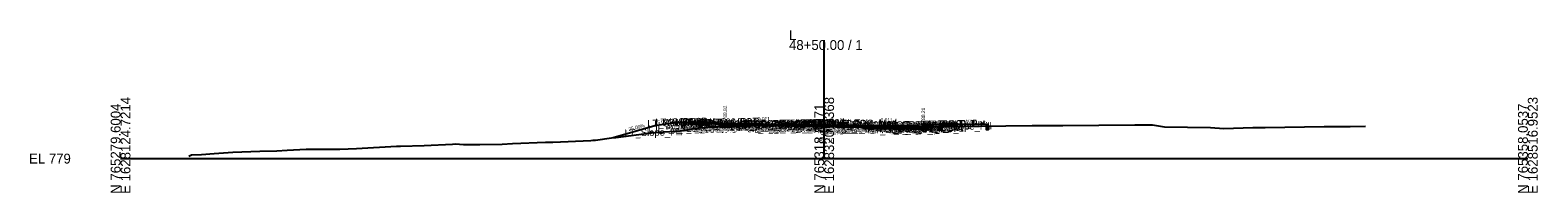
# Model space of a CAD drawing. Extents: x -26 to 4403, y -510 to 9556.
# Drawn here: x 2974.3 to 3402.8, y 8490.3 to 8536.4 of the extents above; entities that cross this region are included whole.
import ezdxf

# ---------------------------------------------------------------- set-up
doc = ezdxf.new("R2010")
doc.units = 0
for name, color, linetype in [('Default', 7, 'Continuous'), ('Exist CMT Pavement', 7, 'Continuous'), ('Exist Cross Section Cell', 7, 'Continuous'), ('Exist XS Center Line Elevation Label', 7, 'Continuous'), ('Exist XS Ground Line', 7, 'Continuous'), ('Prop CMT Conc Surface', 7, 'Continuous'), ('Prop CMT Concrete Structures', 7, 'Continuous'), ('Prop CMT Pvmt Course 1', 7, 'Continuous'), ('Prop CMT Pvmt Course 1 CG', 7, 'Continuous'), ('Prop CMT Pvmt Course 2', 7, 'Continuous'), ('Prop CMT Pvmt Course 2 Wedge', 7, 'Continuous'), ('Prop CMT Pvmt Course 3', 7, 'Continuous'), ('Prop CMT Pvmt Course 3 Wedge', 7, 'Continuous'), ('Prop CMT Pvmt Surface', 7, 'Continuous'), ('Prop CMT Slope Grass', 7, 'Continuous'), ('Prop CMT Subgrade Earthwork', 7, 'Continuous'), ('Prop XS Finish Grade CurbGutter', 7, 'Continuous'), ('Prop XS Hydro Elevations', 7, 'Continuous'), ('Prop XS SE Text', 7, 'Continuous'), ('Prop XS Side Slope Text', 7, 'Continuous'), ('Scratch_Level_0', 7, 'Continuous')]:
    doc.layers.add(name, color=color, linetype=linetype)

msp = doc.modelspace()

# ---------------------------------------------------------------- linework, layer by layer
at = {"layer": 'Exist CMT Pavement'}
for points in [[(3173.85, 8509.18), (3174.11, 8509.18), (3182.2, 8509.38), (3190.56, 8509.3), (3191.23, 8509.29)], [(3208.77, 8508.96), (3209.39, 8508.97), (3211.08, 8508.98)]]:
    msp.add_lwpolyline(points, dxfattribs=at)
at = {"layer": 'Exist Cross Section Cell'}
for p, q in [((3200, 8500), (3200, 8533.6)), ((3000, 8500), (3200, 8500)), ((3200, 8500), (3400, 8500))]:
    msp.add_line(p, q, dxfattribs=at)
at = {"layer": 'Exist XS Ground Line'}
msp.add_lwpolyline([(3019.39, 8500.67), (3020.16, 8501.04), (3022.97, 8501.2), (3026.61, 8501.44), (3031.94, 8501.81), (3034.49, 8501.96), (3039.59, 8502.09), (3044.44, 8502.17), (3047.32, 8502.39), (3052.78, 8502.71), (3062.34, 8502.68), (3067.05, 8502.9), (3078.43, 8503.49), (3079.57, 8503.52), (3086.29, 8503.75), (3094.36, 8504.13), (3095.16, 8504.14), (3097.51, 8504.01), (3101.17, 8504.01), (3102.14, 8503.99), (3108.47, 8504.07), (3111.41, 8504.32), (3120.76, 8504.62), (3122.88, 8504.69), (3133.66, 8505.11), (3134.31, 8505.21), (3134.97, 8505.27), (3139.58, 8505.85), (3140.77, 8506.02), (3150.92, 8507.33), (3152.79, 8507.48), (3157.72, 8507.73), (3159.04, 8507.89), (3164.97, 8508.77), (3165.57, 8508.68), (3167.07, 8509), (3167.64, 8509.02), (3174.11, 8509.18), (3182.2, 8509.38), (3190.56, 8509.3), (3194.45, 8509.27), (3198.03, 8509.16), (3200, 8509.1), (3206.63, 8508.9), (3209.39, 8508.97), (3237.06, 8509.1), (3241, 8509.17), (3244.18, 8509.2), (3259.12, 8509.37), (3267.85, 8509.39), (3288.26, 8509.53), (3290, 8509.53), (3293.32, 8509.56), (3293.84, 8509.47), (3296.68, 8509), (3309.78, 8508.84), (3313.57, 8508.54), (3321.79, 8508.81), (3325.37, 8508.79), (3342.1, 8509.06), (3348.41, 8509.06), (3349.47, 8509.06), (3353.89, 8509.21)], dxfattribs=at)
at = {"layer": 'Prop CMT Conc Surface'}
for points in [[(3173.85, 8509.88), (3171.85, 8509.82)], [(3226.15, 8509.31), (3228.15, 8509.21)], [(3228.15, 8509.21), (3228.15, 8509.71), (3228.65, 8509.71)], [(3232.66, 8509.8), (3237.66, 8509.9)]]:
    msp.add_lwpolyline(points, dxfattribs=at)
at = {"layer": 'Prop CMT Concrete Structures'}
for p, q in [((3151.85, 8509.25), (3140, 8505.91)), ((3156.85, 8510), (3151.85, 8509.25)), ((3161.85, 8510.2), (3156.85, 8510)), ((3167.35, 8510.09), (3161.85, 8510.2)), ((3171.35, 8509.93), (3167.35, 8510.09)), ((3171.85, 8509.82), (3171.35, 8509.93))]:
    msp.add_line(p, q, dxfattribs=at)
for points in [[(3162.34, 8509.86), (3162.34, 8510.19)], [(3167.34, 8509.76), (3162.34, 8509.86)], [(3167.34, 8510.09), (3167.34, 8509.76)], [(3171.35, 8509.93), (3171.35, 8509.32), (3173.85, 8509.3)], [(3173.85, 8509.3), (3173.85, 8509.88)], [(3226.15, 8509.31), (3228.15, 8509.21), (3228.15, 8509.71), (3228.65, 8509.71)], [(3228.65, 8509.71), (3228.65, 8508.7), (3226.15, 8508.73)], [(3226.15, 8508.73), (3226.15, 8509.31)], [(3237.66, 8509.9), (3232.66, 8509.8)], [(3232.66, 8509.8), (3232.66, 8509.47)], [(3232.66, 8509.47), (3237.66, 8509.57)], [(3237.66, 8509.57), (3237.66, 8509.9)]]:
    msp.add_lwpolyline(points, dxfattribs=at)
at = {"layer": 'Prop CMT Pvmt Course 1'}
for points in [[(3200, 8509.6), (3173.85, 8509.88)], [(3173.85, 8509.88), (3173.85, 8509.63), (3173.85, 8509.63)], [(3173.85, 8509.63), (3200, 8509.35)], [(3200, 8509.6), (3226.15, 8509.31)], [(3200, 8509.35), (3200, 8509.6)], [(3226.15, 8509.06), (3211.09, 8509.22), (3200, 8509.35)], [(3200, 8509.35), (3200, 8509.35)], [(3208.75, 8509.25), (3208.75, 8509.25)], [(3226.15, 8509.31), (3226.15, 8509.06)]]:
    msp.add_lwpolyline(points, dxfattribs=at)
at = {"layer": 'Prop CMT Pvmt Course 1 CG'}
for points in [[(3173.85, 8509.3), (3170.85, 8509.33), (3170.52, 8509)], [(3170.52, 8509), (3173.85, 8508.96)], [(3173.85, 8508.96), (3173.85, 8509.3)], [(3226.15, 8508.73), (3229.15, 8508.7), (3229.49, 8508.36)], [(3226.15, 8508.4), (3226.15, 8508.73)], [(3229.49, 8508.36), (3226.15, 8508.4)]]:
    msp.add_lwpolyline(points, dxfattribs=at)
at = {"layer": 'Prop CMT Pvmt Course 2'}
for points in [[(3173.85, 8509.3), (3173.85, 8509.3), (3173.85, 8509.63), (3173.85, 8509.63)], [(3173.85, 8509.63), (3173.85, 8509.3)], [(3200, 8509.35), (3200, 8509.35)], [(3208.75, 8509.25), (3208.75, 8509.25)], [(3211.09, 8508.89), (3211.09, 8509.22)], [(3211.09, 8509.22), (3226.15, 8509.06)], [(3226.15, 8508.73), (3211.09, 8508.89)], [(3226.15, 8509.06), (3226.15, 8508.73)]]:
    msp.add_lwpolyline(points, dxfattribs=at)
at = {"layer": 'Prop CMT Pvmt Course 2 Wedge'}
for points in [[(3173.85, 8509.63), (3174.11, 8509.63), (3182.2, 8509.54), (3190.56, 8509.45), (3200, 8509.35)], [(3173.85, 8509.29), (3173.85, 8509.63)], [(3191.23, 8509.29), (3190.56, 8509.3), (3182.2, 8509.38), (3177.16, 8509.26), (3174.11, 8509.29), (3173.85, 8509.29)], [(3200, 8509.35), (3200, 8509.1)], [(3200, 8509.35), (3209.39, 8509.24), (3211.09, 8509.22)], [(3211.09, 8508.98), (3209.39, 8508.97), (3208.75, 8508.96)], [(3211.09, 8509.22), (3211.09, 8508.98)]]:
    msp.add_lwpolyline(points, dxfattribs=at)
at = {"layer": 'Prop CMT Pvmt Course 3'}
for points in [[(3173.85, 8509.3), (3173.85, 8509.3), (3173.85, 8508.96), (3173.85, 8508.96)], [(3173.85, 8508.96), (3173.85, 8509.3)], [(3211.09, 8508.89), (3226.15, 8508.73)], [(3211.09, 8508.56), (3211.09, 8508.89)], [(3226.15, 8508.4), (3211.09, 8508.56)], [(3226.15, 8508.73), (3226.15, 8508.4)]]:
    msp.add_lwpolyline(points, dxfattribs=at)
at = {"layer": 'Prop CMT Pvmt Course 3 Wedge'}
for points in [[(3173.85, 8509.3), (3174.11, 8509.29), (3177.17, 8509.26)], [(3173.85, 8509.18), (3173.85, 8509.3)], [(3177.17, 8509.26), (3174.11, 8509.18), (3173.85, 8509.18)]]:
    msp.add_lwpolyline(points, dxfattribs=at)
at = {"layer": 'Prop CMT Pvmt Surface'}
for points in [[(3200, 8509.6), (3173.85, 8509.88)], [(3200, 8509.6), (3226.15, 8509.31)]]:
    msp.add_lwpolyline(points, dxfattribs=at)
at = {"layer": 'Prop CMT Slope Grass'}
for p, q in [((3228.65, 8509.71), (3238.15, 8509.9)), ((3238.15, 8509.9), (3245.99, 8509.72))]:
    msp.add_line(p, q, dxfattribs=at)
msp.add_lwpolyline([(3245.99, 8509.72), (3245.99, 8508.23), (3246.66, 8508.23), (3246.66, 8509.22)], dxfattribs=at)
at = {"layer": 'Prop CMT Subgrade Earthwork'}
for points in [[(3173.85, 8508.96), (3170.52, 8509), (3169.51, 8510)], [(3173.85, 8508.96), (3173.85, 8509.18)], [(3173.85, 8508.96), (3173.85, 8508.96)], [(3173.85, 8508.96), (3173.85, 8508.96)], [(3211.09, 8508.56), (3211.08, 8508.98)], [(3211.09, 8508.56), (3226.15, 8508.4)], [(3226.15, 8508.4), (3229.49, 8508.36), (3230.89, 8509.76)], [(3226.15, 8508.4), (3226.15, 8508.4)]]:
    msp.add_lwpolyline(points, dxfattribs=at)
at = {"layer": 'Prop XS Finish Grade CurbGutter'}
for p, q in [((3245.99, 8509.72), (3246.19, 8509.72)), ((3245.99, 8509.72), (3246.66, 8509.72)), ((3245.99, 8509.72), (3245.99, 8508.73)), ((3245.99, 8508.73), (3245.99, 8508.23)), ((3245.99, 8508.73), (3246.66, 8508.73)), ((3245.99, 8508.23), (3246.66, 8508.23)), ((3246.66, 8509.31), (3246.31, 8509.67)), ((3246.66, 8509.31), (3246.66, 8508.73)), ((3246.66, 8509.22), (3246.66, 8509.22)), ((3246.66, 8508.73), (3246.66, 8508.23))]:
    msp.add_line(p, q, dxfattribs=at)
msp.add_arc((3246.19, 8509.56), 0.166, 43.9997, 90, dxfattribs=at)

# ---------------------------------------------------------------- texts
at = {"layer": 'Default'}
msp.add_text('-', height=0.0001, dxfattribs=at).set_placement((3000, 8500))
at = {"layer": 'Exist Cross Section Cell'}
for s, p in [('L', (3190, 8533.6)), ('48+50.00 / 1', (3190, 8530.8)), ('EL 779', (2974, 8498.6))]:
    msp.add_text(s, height=2.8, dxfattribs=at).set_placement(p)
for s, p in [('N 765279.6004', (3000, 8490)), ('E 1628124.7214', (3002.8, 8490)), ('N 765318.8271', (3200, 8490)), ('E 1628320.8368', (3202.8, 8490)), ('N 765358.0537', (3400, 8490)), ('E 1628516.9523', (3402.8, 8490))]:
    msp.add_text(s, height=2.8, rotation=90, dxfattribs=at).set_placement(p)
at = {"layer": 'Exist XS Center Line Elevation Label'}
msp.add_text('788.10', height=1.2, dxfattribs=at).set_placement((3197.72, 8504.5))
at = {"layer": 'Prop XS Hydro Elevations'}
for s, p in [('788.82', (3172.35, 8510.82)), ('788.21', (3228.65, 8510.21))]:
    msp.add_text(s, height=1, rotation=90, dxfattribs=at).set_placement(p)
at = {"layer": 'Prop XS SE Text'}
for s, rotation, p in [('15.00%', 8.5308, (3151.87, 8509.61)), ('4.00%', 2.2906, (3157.59, 8510.26)), ('2.00%', 358.8542, (3163, 8510.37)), ('4.00%', 357.7094, (3167.22, 8510.41)), ('0.011', 359.381, (3181.11, 8510.8)), ('0.011', 359.381, (3216.02, 8510.42)), ('25.00%', 14.0362, (3144.5, 8507.8))]:
    msp.add_text(s, height=1, rotation=rotation, dxfattribs=at).set_placement(p)
at = {"layer": 'Prop XS Side Slope Text'}
msp.add_text('VAR.', height=1, rotation=358.7026, dxfattribs=at).set_placement((3240.29, 8510.04))
at = {"layer": 'Scratch_Level_0'}
for s, p in [('LT_Sub_Trench_Out_DLT', (3149.74, 8508.98)), ('LT_CSLP_Pnt', (3152.04, 8509.31)), ('48+50.00', (3154.61, 8509.21)), ('48+50.00', (3155.36, 8509.37)), ('LT_CG_Top_Face', (3159.13, 8509.07)), ('LT_CG_Top_BOC', (3159.65, 8509.09)), ('LT_CG_Top_Gut', (3160.11, 8508.58)), ('LT_PV2_OEEOP', (3163.18, 8508.41)), ('48+50.00', (3163.72, 8509.2)), ('LT_PV2_OEOT', (3164.04, 8508.43)), ('LT_PV1_OEOT', (3164.61, 8508.69)), ('48+50.00', (3166.48, 8508.72)), ('LT_CG_Top_Face_Med', (3175.39, 8508.52)), ('LT_CG_Top_Gut_Med', (3176.37, 8508.37)), ('LT_CG_Top_BOC_Med', (3177.18, 8508.79)), ('LT_PV1_PGL', (3183.05, 8508.53)), ('LT_Sub_DLT_In', (3183.96, 8508.92)), ('48+50.00', (3185.27, 8508.59)), ('48+50.00', (3185.85, 8508.91)), ('MD_Crown Point', (3187.09, 8508.98)), ('RT_CG_Top_Face_Med', (3191.34, 8508.34)), ('RT_CG_Top_BOC_Med', (3191.61, 8508.61)), ('48+50.00', (3191.77, 8509.08)), ('RT_CG_Top_Gut_Med', (3192.32, 8508.2)), ('RT_Sub_DLT_In', (3193.92, 8508.8)), ('48+50.00', (3194.65, 8509.05)), ('48+50.00', (3200.37, 8508.8)), ('48+50.00', (3200.57, 8508.77)), ('RT_PV1_PGL', (3200.5, 8508.34)), ('RT_Sub_Trench_Out_DLT', (3211.43, 8508.37)), ('RT_CG_Top_Face', (3215.39, 8508.46)), ('RT_CG_Top_BOC', (3216.91, 8508.48)), ('RT_CSLP_Pnt', (3228.3, 8508.7)), ('48+50.00', (3229.17, 8508.72)), ('LT_Slope_Fill', (3143.28, 8506.28)), ('LT_PV_Sub_Tie_Out', (3150.07, 8507.45)), ('LT_PV_OEEOP_EG', (3152.67, 8507.5)), ('LT_CG1_Shelf_Out', (3157.42, 8508.06)), ('LT_CG_Bot_BOC', (3159.68, 8508.09)), ('LT_Sub_OEOT_CG_1', (3160.09, 8507.69)), ('LT_Sub_OEOP', (3160.65, 8507.8)), ('LT_Sub_OEEOP', (3163.08, 8507.75)), ('LT_PV3_OEEOP', (3163.18, 8508.08)), ('LT_CG_Bot_IE', (3163.78, 8508.09)), ('LT_Sub_OEOT', (3163.95, 8507.76)), ('LT_PV3_OEOT', (3164.04, 8508.1)), ('LT_CG_Bot_BOC_Med', (3177.21, 8507.78)), ('LT_CG_Bot_IE_Med', (3177.34, 8507.83)), ('LT_PV_Sub_Tie_In', (3177.84, 8508.02)), ('LT_Sub_IEOT_CG_1', (3178.14, 8507.51)), ('LT_PV_IEEOP_EG', (3179.46, 8508.06)), ('LT_Sub_IEEOP', (3181.13, 8507.57)), ('LT_PV2_IEEOP', (3181.22, 8508.24)), ('LT_PV3_IEEOP', (3181.22, 8507.91)), ('LT_CG1_Shelf_In', (3181.46, 8507.85)), ('LT_Sub_PGL', (3182.39, 8507.6)), ('LT_PV2_PGL', (3182.48, 8508.26)), ('LT_PV3_PGL', (3182.48, 8507.93)), ('LT_Sub_IEOP', (3184.37, 8507.56)), ('RT_CG_Bot_BOC_Med', (3191.64, 8507.62)), ('RT_CG_Bot_IE_Med', (3194.79, 8507.64)), ('RT_CG1_Shelf_In', (3194.89, 8507.7)), ('RT_PV_Sub_Tie_In', (3195.28, 8507.69)), ('RT_Sub_IEOT_CG_1', (3195.59, 8507.32)), ('RT_PV_Sub_Tie_Out', (3196.03, 8507.68)), ('RT_PV_IEEOP_EG', (3196.91, 8507.72)), ('RT_Sub_IEOP', (3197.14, 8507.42)), ('RT_Sub_IEEOP', (3198.58, 8507.38)), ('RT_PV_OEEOP_EG', (3198.61, 8507.73)), ('RT_PV2_IEEOP', (3198.68, 8508.05)), ('RT_PV3_IEEOP', (3198.68, 8507.72)), ('RT_Sub_PGL', (3199.84, 8507.41)), ('RT_PV2_PGL', (3199.94, 8508.07)), ('RT_PV3_PGL', (3199.94, 8507.74)), ('RT_Sub_OEEOP', (3200.28, 8507.34)), ('RT_PV2_OEEOP', (3200.38, 8508.01)), ('RT_PV3_OEEOP', (3200.38, 8507.68)), ('48+50.00', (3201.26, 8508.4)), ('RT_Sub_OEOT_CG_1', (3212.35, 8507.12)), ('RT_CG1_Shelf_Out', (3215.68, 8507.43)), ('RT_CG_Bot_IE', (3216.04, 8507.53)), ('RT_Sub_OEOT', (3216.21, 8507.2)), ('RT_PV2_OEOT', (3216.3, 8507.87)), ('RT_PV3_OEOT', (3216.3, 8507.53)), ('RT_CG_Top_Gut', (3216.36, 8507.98)), ('RT_PV1_OEOT', (3216.87, 8508.13)), ('RT_CG_Bot_BOC', (3216.94, 8507.47)), ('RT_Sub_OEOP', (3219.57, 8507.16)), ('48+50.00', (3220.33, 8508.13)), ('RT_Slope_Fill', (3230.86, 8507.97))]:
    msp.add_text(s, height=2, rotation=1.1458, dxfattribs=at).set_placement(p)

doc.saveas('drawing.dxf')
